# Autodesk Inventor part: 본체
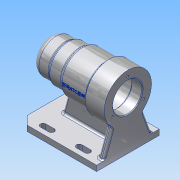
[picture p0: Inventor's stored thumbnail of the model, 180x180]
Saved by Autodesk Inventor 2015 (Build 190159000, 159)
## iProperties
Created: 2017-09
Part Number: 본체
Material: 알루미늄 6061
Document SubType Name: Modeling
Designer: owner
Density: 2.7 g/cm^3
Appearance: 알루미늄 - 평지
Mass: 696.663 g
Surface Area: 709.272 cm^2
Volume: 258.023 cm^3
Author: owner
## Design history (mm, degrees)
sketch "스케치1"
  geometry: C1 r 34 at (0, 0); 1 further point
  constraints: 1 centre point, 1 coincident
  dimensions: "d0" = 68 diameter of C1
extrude "돌출1" new body sketch "스케치1" distance "d1" = 28; taper "d2" = 0 deg
sketch "스케치2"
  geometry: C1 r 34 at (0, 0) reference; C2 r 30 at (0, 0)
  constraints: 1 centre point, 1 coincident
  dimensions: "d3" = 60 diameter of C2
extrude "돌출2" join sketch "스케치2" distance "d4" = 39; taper "d5" = 0 deg
sketch "스케치3"
  geometry: C1 r 30 at (0, 0) reference; C2 r 27 at (0, 0)
  constraints: 1 centre point, 1 coincident
  dimensions: "d6" = 54 diameter of C2
extrude "돌출3" join sketch "스케치3" distance "d7" = 20; taper "d8" = 0 deg
sketch "스케치4"
  geometry: C1 r 27 at (0, 0) reference; C2 r 25 at (0, 0)
  constraints: 1 centre point, 1 coincident
  dimensions: "d9" = 50 diameter of C2
extrude "돌출4" join sketch "스케치4" distance "d10" = 25; taper "d11" = 0 deg
node "작업 평면1"
sketch "스케치5"
  geometry: L1 (0, -34)-(0, 34) reference; L2 (-112, 25)-(-112, -25) reference; L3 (-112, 45)-(0, 45); L4 (0, 45)-(0, -45); L5 (0, -45)-(-112, -45); L6 (-112, -45)-(-112, 45); L7 (-112, 0)-(0, 0); L8 (-112, 0)-(0, 0); 1 further point
  constraints: 12 end point, 5 midpoint, 2 horizontal, 2 parallel, 1 perpendicular
  dimensions: "d13" = 112 distance of L3.start L3.end; "d14" = 90 distance of L3.end L4.end
extrude "돌출5" join sketch "스케치5" distance "d15" = 8; taper "d16" = 0 deg
sketch "스케치6"
  geometry: L1 (-45, -62)-(45, -62) reference; L2 (0, 0)-(0, -62); L3 (-34, 0)-(34, 0); L4 (-35, -62)-(-12.434, 0); L5 (35, -62)-(12.434, 0); L6 (-12.434, 0)-(12.434, 0); L7 (-35, -62)-(35, -62); A1 r 34 centre (0, 0) between (-34, 0) and (34, 0) reference; 1 further point
  constraints: 12 end point, 5 point on line, 2 collinear, 2 midpoint, 2 point on circle, 1 equal length, 1 horizontal
  dimensions: "d17" = 10 distance of L4.start L1.start; "d18" = 10 distance of L1.end L5.start; "d19" = 110 deg angle of L1 L5
extrude "돌출6" join sketch "스케치6" distance "d20" = 8; taper "d21" = 0 deg
sketch "스케치7"
  geometry: L1 (112, -70)-(0, -70) reference; L2 (112, -70)-(112, -62) reference; L3 (0, -62)-(112, -62) reference; L4 (0, -70)-(0, -62) reference; L5 (112, -25)-(112, 25) reference; L6 (87, 25)-(87, -25) reference; L7 (112, 0)-(0, 0); L8 (73.387, 0)-(90, -62); L9 (90, -62)-(0, -62); L10 (73.387, 0)-(0, 0); L11 (0, 0)-(0, -62)
  constraints: 10 end point, 2 collinear, 2 point on line, 1 horizontal, 1 midpoint, 1 vertical
  dimensions: "d22" = 22 distance of L8.end L2.end; "d23" = 105 deg angle of L3 L8
extrude "돌출7" join sketch "스케치7" stored distance "d24" = 8; taper "d25" = 0 deg
sketch "스케치8"
  geometry: L1 (0, -45)-(112, -45) reference; L2 (112, -45)-(112, 45) reference; L3 (112, 45)-(0, 45) reference; L4 (112, 0)-(0, 0); L5 (112, -34)-(0, -34); L6 (24, -45)-(24, 45); L7 (36, -45)-(36, 45); L8 (76, -45)-(76, 45); L9 (88, -45)-(88, 45); L10 (88, -38)-(76, -38); L11 (88, -30)-(76, -30); L12 (36, -38)-(24, -38); L13 (36, -30)-(24, -30); A1 r 4 centre (24, -34) between (24, -30) and (24, -38); A2 r 4 centre (36, -34) between (36, -38) and (36, -30); A3 r 4 centre (76, -34) between (76, -30) and (76, -38); A4 r 4 centre (88, -34) between (88, -38) and (88, -30)
  constraints: 25 point on line, 20 end point, 8 point on circle, 4 centre point, 3 perpendicular, 2 horizontal, 1 midpoint, 1 vertical
  dimensions: "d26" = 34 distance of L5.start L4.start; "d27" = 24 distance of L1.start L6.start; "d28" = 12 distance of L6.start L7.start; "d29" = 40 distance of L8.start L7.start; "d30" = 12 distance of L9.start L8.start; "d31" = 8 diameter of A1; "d32" = 8 diameter of A2; "d33" = 8 diameter of A3; "d34" = 8 diameter of A4
extrude "돌출8" cut sketch "스케치8" distance "d35" = 20; taper "d36" = 0 deg
chamfer "모따기1" distance "d37" = 12; stored, may be unused: second distance "d38" = 2, angle "d39" = 45 deg
sketch "스케치9"
  geometry: C1 r 21 at (0, 0); A1 r 34 centre (0, 0) between (21.9, -26.008) and (-21.9, -26.008) reference
  constraints: 1 centre point, 1 coincident
  dimensions: "d40" = 42 diameter of C1
extrude "돌출9" cut sketch "스케치9" distance "d41" = 15; taper "d42" = 0 deg
sketch "스케치10"
  geometry: C1 r 21 at (0, 0) reference; C2 r 24 at (0, 0)
  constraints: 1 centre point, 1 coincident
  dimensions: "d43" = 48 diameter of C2
extrude "돌출10" cut sketch "스케치10" distance "d44" = 54; taper "d45" = 0 deg
sketch "스케치11"
  geometry: C1 r 24 at (0, 0) reference; C2 r 21 at (0, 0)
  constraints: 1 centre point, 1 coincident
  dimensions: "d46" = 42 diameter of C2
extrude "돌출11" cut sketch "스케치11" distance "d47" = 12; taper "d48" = 0 deg
sketch "스케치12"
  geometry: C1 r 21 at (0, 0) reference; C2 r 17.5 at (0, 0)
  constraints: 1 centre point, 1 coincident
  dimensions: "d49" = 35 diameter of C2
extrude "돌출12" cut sketch "스케치12" distance "d50" = 18; taper "d51" = 0 deg
sketch "스케치13"
  geometry: C1 r 17.5 at (0, 0) reference; C2 r 16 at (0, 0)
  constraints: 1 centre point, 1 coincident
  dimensions: "d52" = 32 diameter of C2
extrude "돌출13" cut sketch "스케치13" distance "d53" = 4; taper "d54" = 0 deg
sketch "스케치14"
  geometry: C1 r 16 at (0, 0) reference; C2 r 10.5 at (0, 0)
  constraints: 1 centre point, 1 coincident
  dimensions: "d55" = 21 diameter of C2
extrude "돌출14" cut sketch "스케치14" distance "d56" = 3; taper "d57" = 0 deg
fillet "모깎기3" dims "d60" = 3
fillet "모깎기4" dims "d61" = 3
fillet "모깎기5" dims "d62" = 1
fillet "모깎기6" dims "d63" = 9
chamfer "모따기2" distance "d64" = 1; stored, may be unused: second distance "d65" = 2, angle "d66" = 45 deg
fillet "모깎기7" dims "d67" = 3
fillet "모깎기8" dims "d68" = 3
fillet "모깎기9" dims "d69" = 3
fillet "모깎기10" dims "d70" = 0.3
fillet "모깎기11" dims "d71" = 3
fillet "모깎기12" dims "d72" = 3
sketch "스케치15" dims "d73" = 52
  geometry: L1 (0, 0)-(0, 26); C1 r 22 at (0, 0) reference; 1 further point
  constraints: 2 coincident, 2 end point, 1 vertical, 1 vertical alignment, 2 other
hole "구멍1" sketch "스케치15" at (0, 26) diameter "d74" = 3.242; stored, may be unused: countersink angle "d78" = 90 deg, drill point angle "d80" = 118 deg; dims "d75" = 8, "d76" = 4, "d77" = 2, "d79" = 11
node "작업축1"
fillet "모깎기13" dims "d84" = 3
node "작업 평면2"
sketch "스케치16"
  geometry: L1 (0, 34)-(0, -25.254) reference; 2 further points
  constraints: 1 horizontal alignment, 1 other
  dimensions: "d86" = 48 distance from line of point (-48, 0) L1
feature "엠보싱1" sketch "스케치16" dims "d0" = 68, "d87" = 0.5, "d88" = 0
node "솔리드1"
mirror "대칭1"
pattern_circular "원형 패턴1" dims angle "d82" = 360 deg
node "투영된 루프1"
node "투영된 루프2"
